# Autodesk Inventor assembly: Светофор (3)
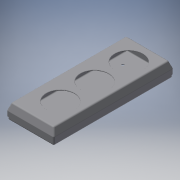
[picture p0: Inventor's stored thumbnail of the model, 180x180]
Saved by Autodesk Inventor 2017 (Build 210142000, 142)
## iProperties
Part Number: Светофор (3)
Material: Типовые
Document SubType Name: Assembly
Designer: Система Знаний
Author: Система Знаний
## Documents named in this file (3)
- C:\Users\Система Знаний\Documents\Светофор (3).iam
- C:\Users\Система Знаний\Documents\Коробка светофора (3).ipt
- C:\Users\Система Знаний\Documents\Крышка светофора (3).ipt
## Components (2 placed, 2 different names)
1. Коробка светофора (3):1 — Совмещение:1
2. Крышка светофора (3):1 — Совмещение:1
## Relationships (1: Mate 1)
- Совмещение:1 [Mate]: Коробка светофора (3):1 ↔ Крышка светофора (3):1
